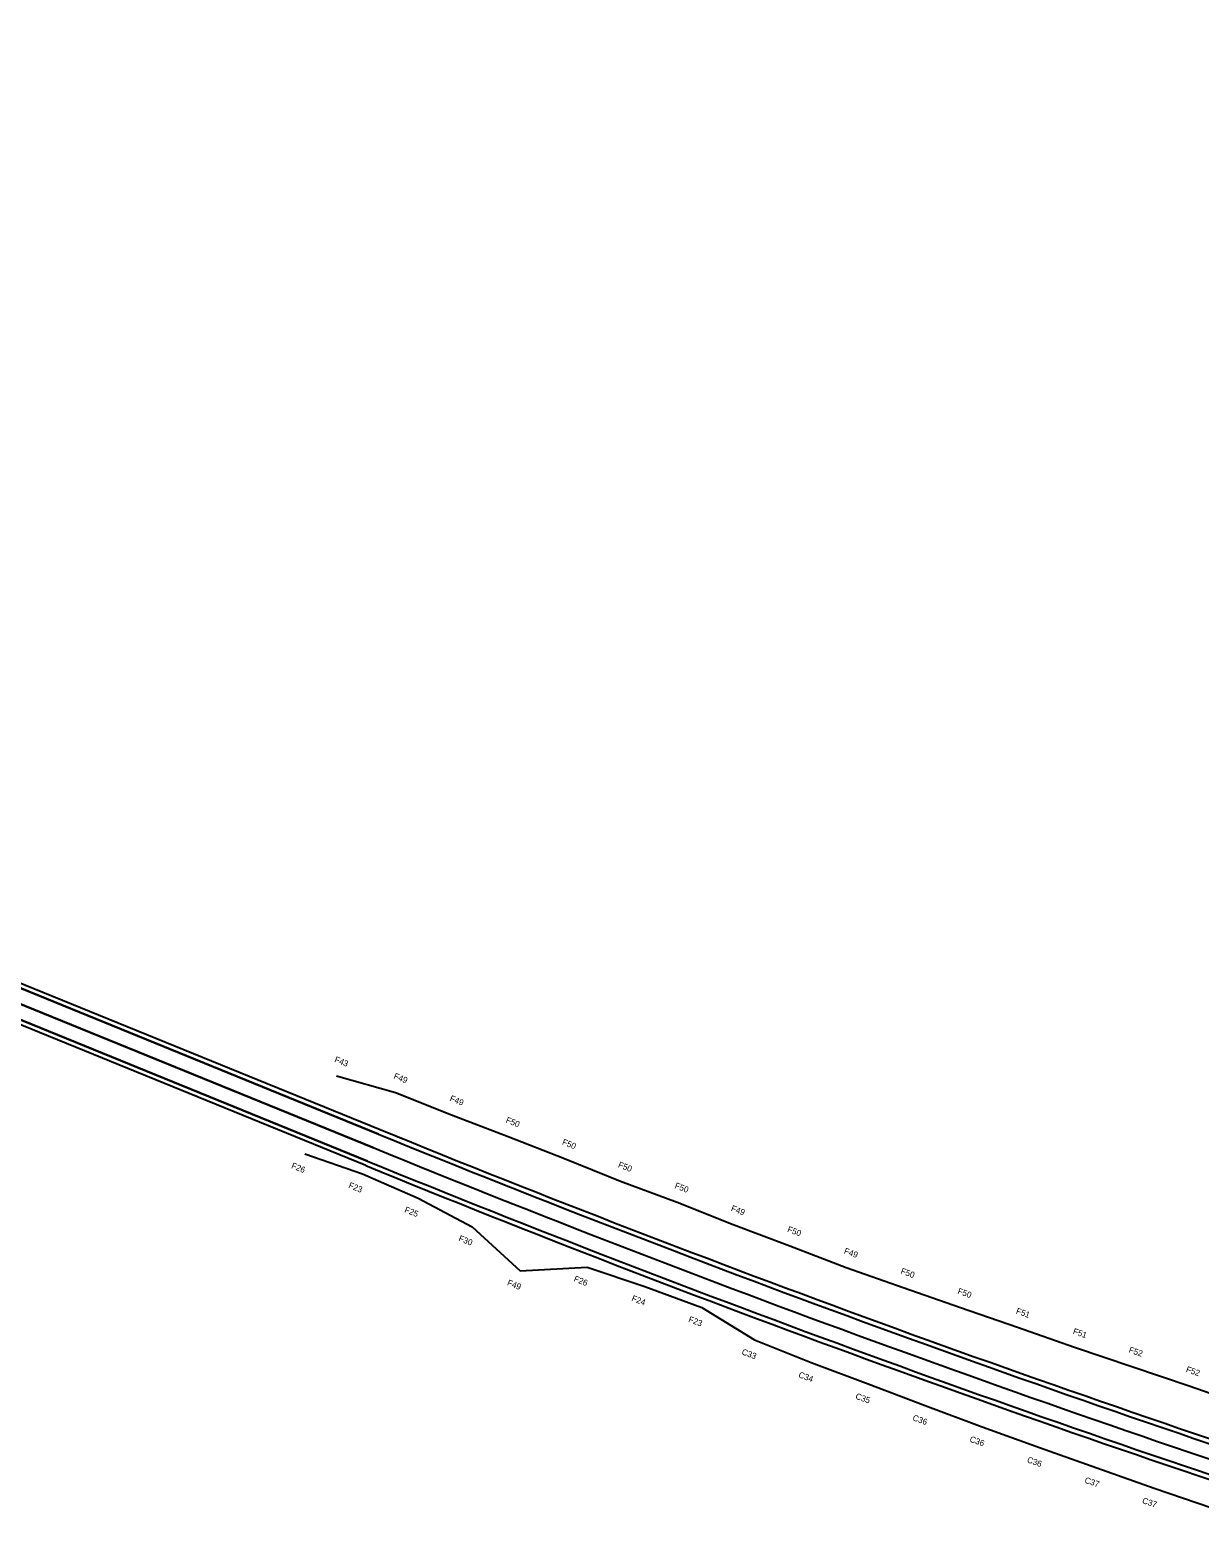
# Model space of a CAD drawing. Extents: x 2163527 to 2171930, y 206045 to 210376.
# Drawn here: x 2165474 to 2166437, y 209136 to 210374 of the extents above; entities that cross this region are included whole.
import ezdxf

# ---------------------------------------------------------------- set-up
doc = ezdxf.new("R2010")
doc.units = 0
for name, color, linetype in [('Default', 7, 'Continuous'), ('RD_PD_CstnLmt', 7, 'Continuous'), ('RD_PD_TX_CstnLmt', 7, 'Continuous')]:
    doc.layers.add(name, color=color, linetype=linetype)

msp = doc.modelspace()

# ---------------------------------------------------------------- linework, layer by layer
at = {"layer": 'Default'}
for p, q in [((2165760.5, 209465.4), (2163537.8, 210370.7)), ((2163537.8, 210370.7), (2165760.5, 209465.4)), ((2163539.3, 210374.4), (2165762, 209469.1)), ((2165756, 209454.3), (2163533.3, 210359.6)), ((2163533.3, 210359.6), (2165756, 209454.3)), ((2165750, 209439.5), (2163527.3, 210344.8)), ((2165751.5, 209443.2), (2163528.8, 210348.5)), ((2163528.8, 210348.5), (2165751.5, 209443.2))]:
    msp.add_line(p, q, dxfattribs=at)
for radius in [11988, 11988, 11984, 12000, 12000, 12016, 12012, 12012]:
    msp.add_arc((2170282.6, 220567.8), radius, 247.83882, 252.05663, dxfattribs=at)
at = {"layer": 'RD_PD_CstnLmt'}
for p, q in [((2165726, 209513.3), (2165774.5, 209499.8)), ((2165774.5, 209499.8), (2165820.8, 209481.4)), ((2165820.8, 209481.4), (2165867.3, 209463.5)), ((2165867.3, 209463.5), (2165913.7, 209445.4)), ((2165699.9, 209449.1), (2165747.3, 209432.8)), ((2165913.7, 209445.4), (2165959.8, 209426.7)), ((2165747.3, 209432.8), (2165793.2, 209412.8)), ((2165959.8, 209426.7), (2166006.5, 209409.5)), ((2165793.2, 209412.8), (2165837.7, 209389.2)), ((2166006.5, 209409.5), (2166052.7, 209390.9)), ((2165837.7, 209389.2), (2165877.3, 209352.9)), ((2166052.7, 209390.9), (2166099.4, 209373.5)), ((2166099.4, 209373.5), (2166145.9, 209355.7)), ((2165877.3, 209352.9), (2165932.4, 209356)), ((2165932.4, 209356), (2165979.9, 209340)), ((2166145.9, 209355.7), (2166192.9, 209339.1)), ((2165979.9, 209340), (2166026.9, 209322.7)), ((2166192.9, 209339.1), (2166239.9, 209322.7)), ((2166026.9, 209322.7), (2166070.4, 209296)), ((2166239.9, 209322.7), (2166287, 209306.6)), ((2166287, 209306.6), (2166333.9, 209289.9)), ((2166070.4, 209296), (2166117, 209277.3)), ((2166333.9, 209289.9), (2166381.1, 209274.2)), ((2166117, 209277.3), (2166163.9, 209259.7)), ((2166381.1, 209274.2), (2166428.3, 209258.1)), ((2166163.9, 209259.7), (2166210.8, 209242)), ((2166428.3, 209258.1), (2166475.3, 209241.9)), ((2166210.8, 209242), (2166257.8, 209224.5)), ((2166257.8, 209224.5), (2166305, 209207.5)), ((2166305, 209207.5), (2166352.3, 209190.7)), ((2166352.3, 209190.7), (2166399.6, 209174)), ((2166399.6, 209174), (2166447, 209157.6))]:
    msp.add_line(p, q, dxfattribs=at)

# ---------------------------------------------------------------- texts
at = {"layer": 'RD_PD_TX_CstnLmt'}
for s, rotation, p in [('F43', 337.8388, (2165723.8, 209525)), ('F49', 337.8388, (2165772.6, 209511.4)), ('F49', 338.0776, (2165818.8, 209493)), ('F50', 338.3163, (2165865, 209475.1)), ('F50', 338.555, (2165911.4, 209457)), ('F26', 337.8388, (2165688.3, 209437.6)), ('F50', 338.7938, (2165957.5, 209438.3)), ('F23', 337.8388, (2165735.4, 209421.4)), ('F50', 339.0325, (2166004.1, 209421.1)), ('F25', 338.0776, (2165781.5, 209401.3)), ('F49', 339.2712, (2166050.5, 209402.4)), ('F50', 339.51, (2166096.9, 209385.1)), ('F30', 338.3163, (2165826.1, 209377.7)), ('F49', 339.7487, (2166143.6, 209367.3)), ('F50', 339.9874, (2166190.3, 209350.7)), ('F49', 338.555, (2165866.1, 209341.2)), ('F26', 338.7938, (2165921, 209344.4)), ('F50', 340.2261, (2166237.2, 209334.2)), ('F24', 339.0325, (2165968.6, 209328.3)), ('F23', 339.2712, (2166015.4, 209311)), ('F51', 340.4649, (2166285.3, 209317.8)), ('F51', 340.7036, (2166332.2, 209301.1)), ('C33', 339.51, (2166059.3, 209284.2)), ('F52', 340.9423, (2166378.2, 209285.8)), ('C34', 339.7487, (2166106.1, 209265.3)), ('F52', 341.1811, (2166425.3, 209269.7)), ('C35', 339.9874, (2166153, 209247.7)), ('C36', 340.2261, (2166200.1, 209229.9)), ('C36', 340.4649, (2166247.1, 209212.3)), ('C36', 340.7036, (2166294.4, 209195.3)), ('C37', 340.9423, (2166341.8, 209178.5)), ('C37', 341.1811, (2166389.2, 209161.7))]:
    msp.add_text(s, height=5, rotation=rotation, dxfattribs=at).set_placement(p)

doc.saveas('drawing.dxf')
